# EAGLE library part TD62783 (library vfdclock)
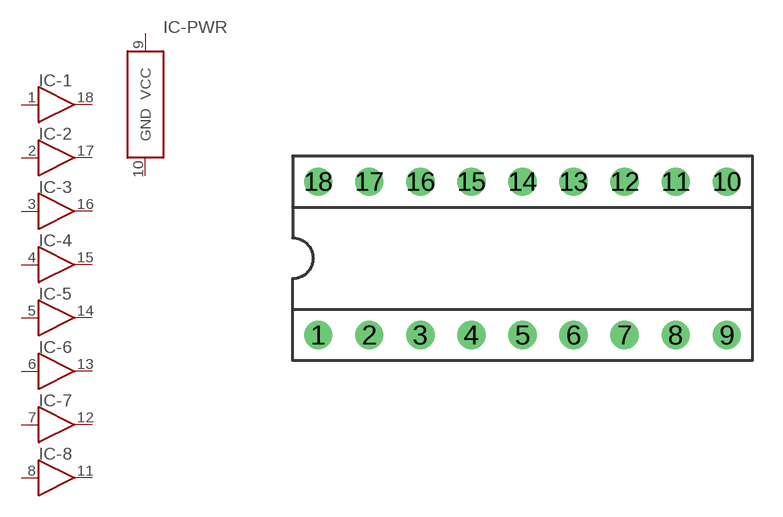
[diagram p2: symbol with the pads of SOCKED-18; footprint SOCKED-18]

Designator prefix IC; gates -1=TD62783 -2=TD62783 -3=TD62783 -4=TD62783 -5=TD62783 -6=TD62783 -7=TD62783 -8=TD62783 -PWR=TD62783_SUP

## TD62783AP  [SOCKED-18]
1  -1:IN  in
2  -2:IN  in
3  -3:IN  in
4  -4:IN  in
5  -5:IN  in
6  -6:IN  in
7  -7:IN  in
8  -8:IN  in
9  -PWR:VCC  pwr
10  -PWR:GND  pwr
11  -8:OUT  out
12  -7:OUT  out
13  -6:OUT  out
14  -5:OUT  out
15  -4:OUT  out
16  -3:OUT  out
17  -2:OUT  out
18  -1:OUT  out

## Footprint SOCKED-18 (pad centres in mm)
Dual In Line Socket
drill 0.9 round: 1 -10.16,-3.81; 2 -7.62,-3.81; 3 -5.08,-3.81; 4 -2.54,-3.81; 5 0,-3.81; 6 2.54,-3.81; 7 5.08,-3.81; 8 7.62,-3.81; 9 10.16,-3.81; 10 10.16,3.81; 11 7.62,3.81; 12 5.08,3.81; 13 2.54,3.81; 14 0,3.81; 15 -2.54,3.81; 16 -5.08,3.81; 17 -7.62,3.81; 18 -10.16,3.81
